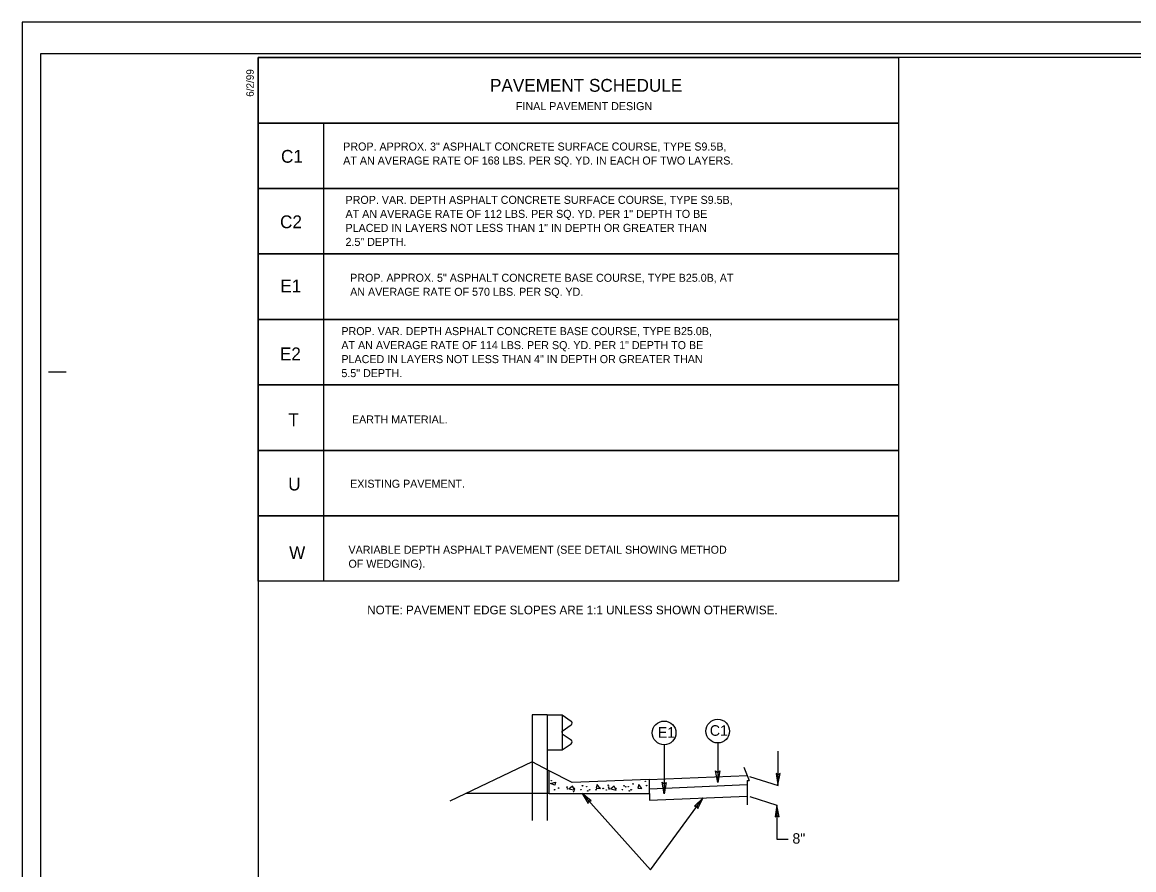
# Model space of a CAD drawing. Extents: x 1733676 to 1734289, y 540979 to 541226.
# Drawn here: x 1734084.6 to 1734169.6, y 541161.1 to 541225.9 of the extents above; entities that cross this region are included whole.
import ezdxf

# ---------------------------------------------------------------- set-up
doc = ezdxf.new("R2010")
doc.units = 0
for name, color, linetype in [('Default', 7, 'Continuous'), ('Old_Level_11', 7, 'Continuous'), ('Prop Dimension', 7, 'Continuous'), ('Prop Pavement Schedule Description CELL', 7, 'Continuous'), ('Sheet Cutting Line CELL', 7, 'Continuous'), ('Sheet Plot Border Inside CELL', 7, 'Continuous'), ('Sheet Plot Border Outside CELL', 7, 'Continuous'), ('Sheet Typical CELL', 7, 'Continuous'), ('Typical Curb CELL', 7, 'Continuous'), ('Typical Detail Wedge2 CELL', 7, 'Continuous'), ('Typical Guardrail CELL', 7, 'Continuous'), ('Typical ID Circle CELL', 7, 'Continuous'), ('Typical Pavement Slope CELL', 7, 'Continuous'), ('Typical Pavement Slope Information CELL', 7, 'Continuous'), ('Typical Terminator CELL', 7, 'Continuous'), ('Typical Text ID Circle CELL', 7, 'Continuous')]:
    doc.layers.add(name, color=color, linetype=linetype)

msp = doc.modelspace()

# ---------------------------------------------------------------- linework, layer by layer
at = {"layer": 'Old_Level_11'}
for points in [[(1734142.25, 541168.444), (1734142.391, 541167.568), (1734142.556, 541168.445), (1734142.4, 541168.335)], [(1734128.123, 541166.364), (1734127.427, 541166.914), (1734127.899, 541166.156), (1734127.94, 541166.343)], [(1734136.275, 541165.777), (1734136.67, 541166.571), (1734136.026, 541165.953), (1734136.217, 541165.952)], [(1734142.479, 541165.135), (1734142.322, 541166.009), (1734142.173, 541165.128), (1734142.328, 541165.241)]]:
    msp.add_lwpolyline(points, close=True, dxfattribs=at)
at = {"layer": 'Prop Dimension'}
for p, q in [((1734142.391, 541170.152), (1734142.391, 541167.568)), ((1734132.655, 541161.084), (1734127.427, 541166.914)), ((1734132.655, 541161.084), (1734136.67, 541166.571)), ((1734140.24, 541166.673), (1734142.322, 541166.009)), ((1734142.322, 541166.009), (1734142.322, 541163.427)), ((1734142.322, 541163.427), (1734143.166, 541163.427))]:
    msp.add_line(p, q, dxfattribs=at)
at = {"layer": 'Prop Pavement Schedule Description CELL'}
msp.add_line((1734107.681, 541183.137), (1734107.681, 541183.137), dxfattribs=at)
msp.add_lwpolyline([(1734102.677, 541223.175), (1734151.614, 541223.175), (1734151.614, 541218.17), (1734102.677, 541218.17)], close=True, dxfattribs=at)
for points in [[(1734107.681, 541213.166), (1734102.677, 541213.166), (1734102.677, 541218.17), (1734151.614, 541218.17), (1734151.614, 541213.166), (1734107.681, 541213.166), (1734107.681, 541218.17)], [(1734107.681, 541208.161), (1734102.677, 541208.161), (1734102.677, 541213.166), (1734151.614, 541213.166), (1734151.614, 541208.161), (1734107.681, 541208.161), (1734107.681, 541213.166)], [(1734107.681, 541203.156), (1734102.677, 541203.156), (1734102.677, 541208.161), (1734151.614, 541208.161), (1734151.614, 541203.156), (1734107.681, 541203.156), (1734107.681, 541208.161)], [(1734107.681, 541198.152), (1734102.677, 541198.152), (1734102.677, 541203.156), (1734151.614, 541203.156), (1734151.614, 541198.152), (1734107.681, 541198.152), (1734107.681, 541203.156)], [(1734107.681, 541193.147), (1734102.677, 541193.147), (1734102.677, 541198.152), (1734151.613, 541198.152), (1734151.613, 541193.147), (1734107.681, 541193.147), (1734107.681, 541198.152)], [(1734107.681, 541188.142), (1734102.677, 541188.142), (1734102.677, 541193.147), (1734151.613, 541193.147), (1734151.613, 541188.142), (1734107.681, 541188.142), (1734107.681, 541193.147)], [(1734107.681, 541183.137), (1734102.677, 541183.137), (1734102.677, 541188.142), (1734151.613, 541188.142), (1734151.613, 541183.137), (1734107.681, 541183.137), (1734107.681, 541188.142)]]:
    msp.add_lwpolyline(points, dxfattribs=at)
at = {"layer": 'Sheet Cutting Line CELL'}
for p, q in [((1734266.513, 541225.875), (1734084.641, 541225.875)), ((1734084.641, 541225.875), (1734084.641, 541107.075))]:
    msp.add_line(p, q, dxfattribs=at)
at = {"layer": 'Sheet Plot Border Inside CELL'}
msp.add_lwpolyline([(1734266.027, 541223.451), (1734086.045, 541223.451), (1734086.045, 541109.5), (1734266.027, 541109.5)], close=True, dxfattribs=at)
at = {"layer": 'Sheet Plot Border Outside CELL'}
msp.add_lwpolyline([(1734266.513, 541225.875), (1734084.641, 541225.875), (1734084.641, 541107.075), (1734266.513, 541107.075)], close=True, dxfattribs=at)
at = {"layer": 'Sheet Typical CELL'}
msp.add_line((1734086.639, 541199.145), (1734087.989, 541199.145), dxfattribs=at)
msp.add_lwpolyline([(1734264.677, 541223.175), (1734102.677, 541223.175), (1734102.677, 541109.775), (1734264.677, 541109.775)], close=True, dxfattribs=at)
at = {"layer": 'Typical Curb CELL'}
for p, q in [((1734124.912, 541166.914), (1734124.912, 541168.635)), ((1734126.658, 541167.761), (1734124.912, 541168.635)), ((1734125.004, 541167.674), (1734125.396, 541167.788)), ((1734125.354, 541167.557), (1734125.004, 541167.674)), ((1734125.396, 541167.788), (1734125.354, 541167.557)), ((1734132.559, 541167.972), (1734126.658, 541167.761)), ((1734128.59, 541167.605), (1734128.503, 541167.316)), ((1734128.807, 541167.3), (1734128.59, 541167.605)), ((1734131.764, 541167.605), (1734131.676, 541167.316)), ((1734131.983, 541167.3), (1734131.764, 541167.605)), ((1734132.586, 541167.973), (1734132.586, 541167.973)), ((1734132.586, 541166.914), (1734132.586, 541167.946)), ((1734124.912, 541166.914), (1734132.586, 541166.914)), ((1734126.706, 541167.462), (1734126.444, 541167.271)), ((1734126.444, 541167.271), (1734126.865, 541167.171)), ((1734126.865, 541167.171), (1734126.706, 541167.462)), ((1734128.503, 541167.316), (1734128.807, 541167.3)), ((1734129.879, 541167.462), (1734129.617, 541167.271)), ((1734129.617, 541167.271), (1734130.038, 541167.171)), ((1734130.038, 541167.171), (1734129.879, 541167.462)), ((1734131.676, 541167.316), (1734131.983, 541167.3))]:
    msp.add_line(p, q, dxfattribs=at)
for centre in [(1734125.076, 541167.891), (1734129.429, 541167.548), (1734131.329, 541167.65), (1734132.262, 541167.84), (1734132.358, 541167.521), (1734125.323, 541167.197), (1734125.628, 541167.325), (1734126.281, 541167.398), (1734126.324, 541167.27), (1734126.774, 541167.052), (1734126.846, 541167.311), (1734127.34, 541167.211), (1734127.459, 541167.504), (1734127.778, 541167.432), (1734127.862, 541167.11), (1734128.004, 541167.197), (1734128.497, 541167.197), (1734128.802, 541167.325), (1734129.04, 541167.301), (1734129.284, 541167.185), (1734129.454, 541167.398), (1734129.498, 541167.27), (1734130.02, 541167.311), (1734130.513, 541167.211), (1734130.633, 541167.504), (1734130.76, 541167.427), (1734130.952, 541167.432), (1734131.036, 541167.11), (1734131.178, 541167.197)]:
    msp.add_circle(centre, 0.0204, dxfattribs=at)
msp.add_arc((1734132.56, 541167.946), 0.0265, 0, 92.04801, dxfattribs=at)
at = {"layer": 'Typical Detail Wedge2 CELL'}
msp.add_line((1734140.23, 541168.215), (1734142.403, 541167.522), dxfattribs=at)
at = {"layer": 'Typical Guardrail CELL'}
for p, q in [((1734124.764, 541172.923), (1734123.615, 541172.923)), ((1734123.615, 541172.923), (1734123.615, 541166.914)), ((1734124.764, 541172.923), (1734124.764, 541166.914)), ((1734124.764, 541172.923), (1734125.913, 541172.923)), ((1734125.913, 541172.923), (1734125.913, 541170.243)), ((1734125.913, 541172.923), (1734126.581, 541172.454)), ((1734125.913, 541171.691), (1734126.581, 541172.16)), ((1734125.913, 541171.583), (1734125.913, 541171.691)), ((1734125.913, 541171.583), (1734125.913, 541171.475)), ((1734125.913, 541171.475), (1734126.581, 541171.006)), ((1734124.764, 541170.243), (1734125.913, 541170.243)), ((1734125.913, 541170.243), (1734126.581, 541170.712)), ((1734123.615, 541166.914), (1734123.615, 541164.851)), ((1734124.764, 541166.914), (1734124.764, 541164.851))]:
    msp.add_line(p, q, dxfattribs=at)
for centre, start, end in [((1734126.479, 541172.307), 304.9888, 54.99703), ((1734126.479, 541170.859), 304.9634, 54.9941)]:
    msp.add_arc(centre, 0.179, start, end, dxfattribs=at)
at = {"layer": 'Typical ID Circle CELL'}
for p, q in [((1734133.696, 541170.636), (1734133.696, 541166.884)), ((1734137.794, 541170.777), (1734137.794, 541167.757))]:
    msp.add_line(p, q, dxfattribs=at)
for centre in [(1734133.696, 541171.543), (1734137.794, 541171.684)]:
    msp.add_circle(centre, 0.906, dxfattribs=at)
at = {"layer": 'Typical Pavement Slope CELL'}
for p, q in [((1734123.615, 541169.336), (1734117.327, 541166.337)), ((1734124.912, 541168.635), (1734123.615, 541169.336)), ((1734132.559, 541167.972), (1734140.048, 541168.284)), ((1734132.586, 541167.282), (1734140.055, 541167.593)), ((1734132.586, 541166.914), (1734132.586, 541166.401)), ((1734132.586, 541166.401), (1734140.055, 541166.712))]:
    msp.add_line(p, q, dxfattribs=at)
at = {"layer": 'Typical Pavement Slope Information CELL'}
for p, q in [((1734139.784, 541168.915), (1734140.205, 541167.909)), ((1734140.055, 541167.909), (1734140.205, 541167.909)), ((1734140.055, 541167.909), (1734140.055, 541166.046)), ((1734124.912, 541166.914), (1734118.538, 541166.914))]:
    msp.add_line(p, q, dxfattribs=at)
at = {"layer": 'Typical Terminator CELL'}
for points in [[(1734137.945, 541168.636), (1734137.794, 541167.757), (1734137.637, 541168.641), (1734137.794, 541168.528)], [(1734133.848, 541167.763), (1734133.696, 541166.884), (1734133.54, 541167.768), (1734133.696, 541167.656)]]:
    msp.add_lwpolyline(points, close=True, dxfattribs=at)

# ---------------------------------------------------------------- texts
at = {"layer": 'Default'}
msp.add_text('FINAL PAVEMENT DESIGN', height=0.6117, dxfattribs=at).set_placement((1734122.374, 541219.155))
at = {"layer": 'Prop Pavement Schedule Description CELL'}
for s, height, p in [('PAVEMENT SCHEDULE', 0.97872, (1734120.392, 541220.56)), ('C1', 0.9787, (1734104.416, 541215.133)), ('PROP. APPROX. 3" ASPHALT CONCRETE SURFACE COURSE, TYPE S9.5B,', 0.6117, (1734109.171, 541216.068)), ('AT AN AVERAGE RATE OF 168 LBS. PER SQ. YD. IN EACH OF TWO LAYERS.', 0.6117, (1734109.171, 541214.997)), ('PROP. VAR. DEPTH ASPHALT CONCRETE SURFACE COURSE, TYPE S9.5B,', 0.6117, (1734109.349, 541211.989)), ('C2', 0.9787, (1734104.346, 541210.128)), ('AT AN AVERAGE RATE OF 112 LBS. PER SQ. YD. PER 1" DEPTH TO BE', 0.6117, (1734109.349, 541210.919)), ('PLACED IN LAYERS NOT LESS THAN 1" IN DEPTH OR GREATER THAN', 0.6117, (1734109.349, 541209.849)), ('2.5" DEPTH.', 0.6117, (1734109.349, 541208.779)), ('PROP. APPROX. 5" ASPHALT CONCRETE BASE COURSE, TYPE B25.0B, AT', 0.6117, (1734109.703, 541206.033)), ('E1', 0.9787, (1734104.369, 541205.228)), ('AN AVERAGE RATE OF 570 LBS. PER SQ. YD.', 0.6117, (1734109.703, 541204.962)), ('PROP. VAR. DEPTH ASPHALT CONCRETE BASE COURSE, TYPE B25.0B,', 0.6117, (1734109.033, 541201.954)), ('E2', 0.9787, (1734104.333, 541200.031)), ('AT AN AVERAGE RATE OF 114 LBS. PER SQ. YD. PER 1" DEPTH TO BE', 0.6117, (1734109.033, 541200.884)), ('PLACED IN LAYERS NOT LESS THAN 4" IN DEPTH OR GREATER THAN', 0.6117, (1734109.033, 541199.814)), ('5.5" DEPTH.', 0.6117, (1734109.033, 541198.743)), ('T', 0.979, (1734104.983, 541194.994)), ('EARTH MATERIAL.', 0.6117, (1734109.841, 541195.2)), ('U', 0.979, (1734104.969, 541190.08)), ('EXISTING PAVEMENT.', 0.6117, (1734109.701, 541190.288)), ('W', 0.979, (1734105.038, 541184.842)), ('VARIABLE DEPTH ASPHALT PAVEMENT (SEE DETAIL SHOWING METHOD', 0.6117, (1734109.574, 541185.243)), ('OF WEDGING).', 0.6117, (1734109.574, 541184.173)), ('NOTE: PAVEMENT EDGE SLOPES ARE 1:1 UNLESS SHOWN OTHERWISE.', 0.66574, (1734111.007, 541180.61))]:
    msp.add_text(s, height=height, dxfattribs=at).set_placement(p)
at = {"layer": 'Sheet Typical CELL'}
msp.add_text('6/2/99', height=0.567, rotation=90, dxfattribs=at).set_placement((1734102.336, 541220.178))
at = {"layer": 'Typical Detail Wedge2 CELL'}
msp.add_text('8"', height=0.8, dxfattribs=at).set_placement((1734143.507, 541163.077))
at = {"layer": 'Typical Text ID Circle CELL'}
for s, p in [('E1', (1734133.206, 541171.176)), ('C1', (1734137.189, 541171.324))]:
    msp.add_text(s, height=0.8112, dxfattribs=at).set_placement(p)

doc.saveas('drawing.dxf')
